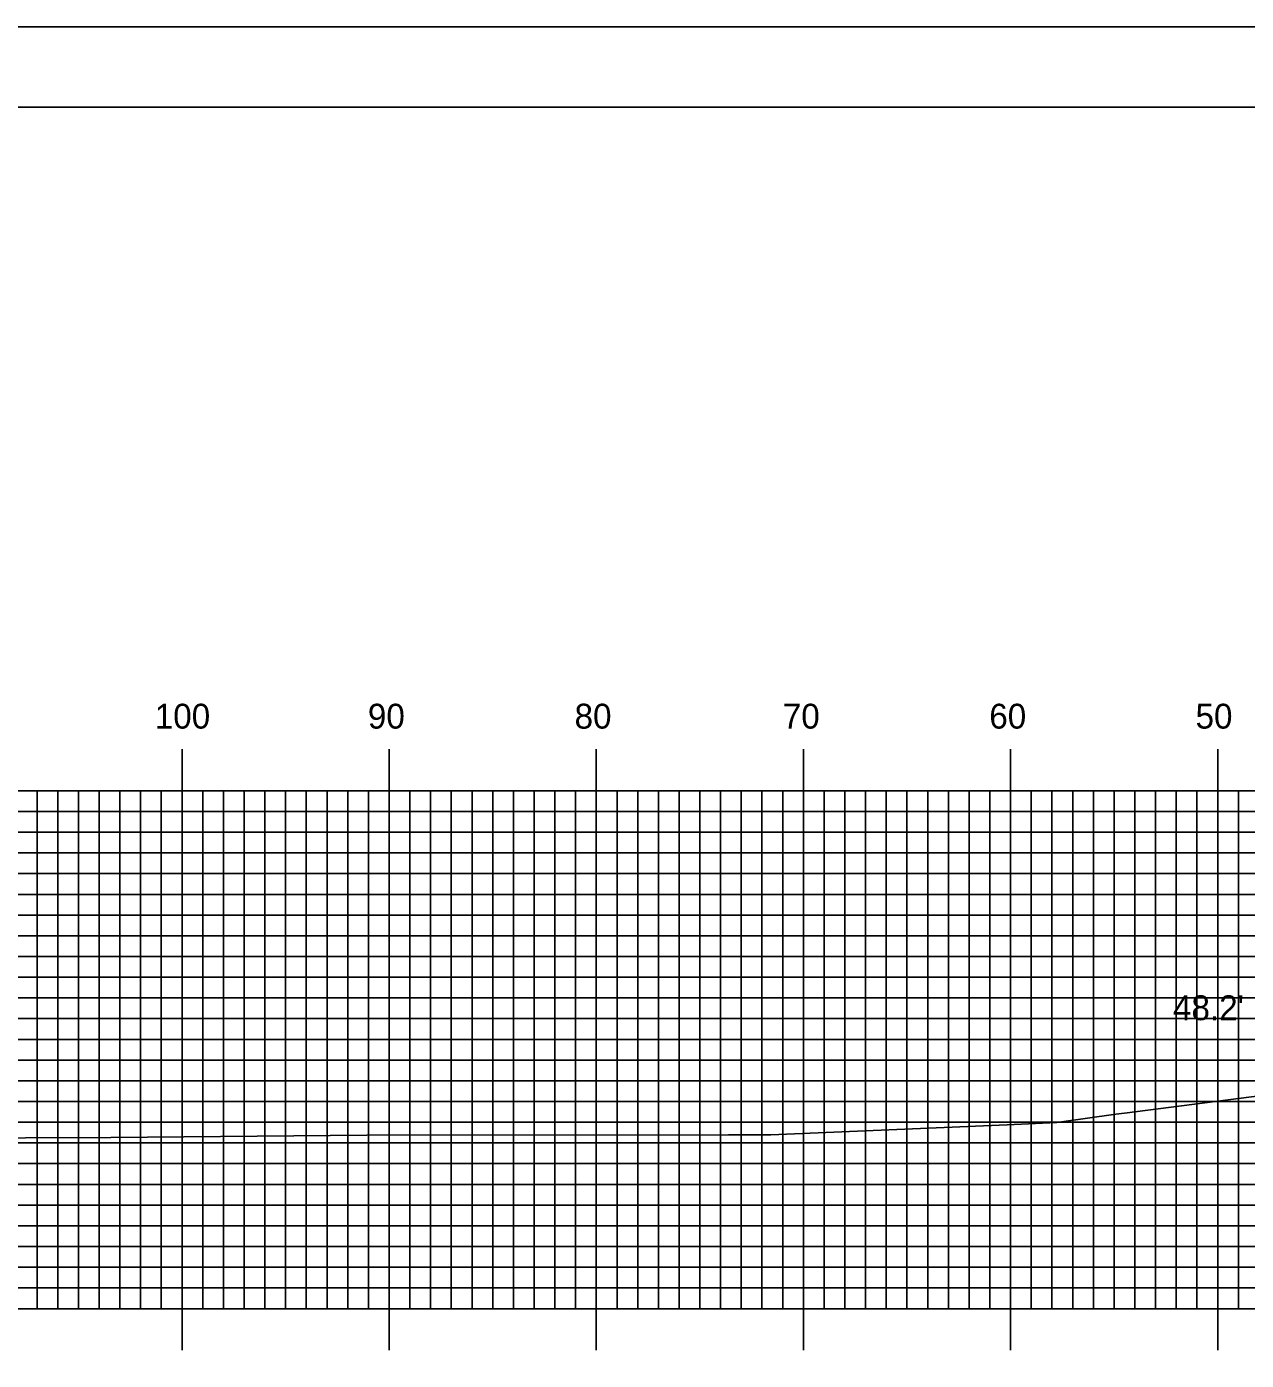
# Model space of a CAD drawing. Extents: x 1824360 to 1824703, y 442591 to 442811.
# Drawn here: x 1824417.8 to 1824476.7, y 442746.2 to 442810.5 of the extents above; entities that cross this region are included whole.
import ezdxf

# ---------------------------------------------------------------- set-up
doc = ezdxf.new("R2010")
doc.units = 0
for name, color, linetype in [('BORDER', 7, 'Continuous'), ('D_Text_Standard', 7, 'Continuous'), ('H_V ANNOTATION', 7, 'Continuous'), ('MAJOR', 7, 'Continuous'), ('MINOR', 7, 'Continuous'), ('PLOT BOUNDARY', 7, 'Continuous'), ('S_Roadway_Centerline', 7, 'Continuous')]:
    doc.layers.add(name, color=color, linetype=linetype)

msp = doc.modelspace()

# ---------------------------------------------------------------- linework, layer by layer
at = {"layer": 'BORDER'}
msp.add_lwpolyline([(1824375.735, 442596.665), (1824695.735, 442596.665), (1824695.735, 442806.665), (1824375.735, 442806.665)], close=True, dxfattribs=at)
at = {"layer": 'MAJOR'}
for p, q in [((1824425.335, 442775.669), (1824425.335, 442773.665)), ((1824435.335, 442775.669), (1824435.335, 442773.665)), ((1824445.335, 442775.669), (1824445.335, 442773.665)), ((1824455.335, 442775.669), (1824455.335, 442773.665)), ((1824465.335, 442775.669), (1824465.335, 442773.665)), ((1824475.335, 442775.669), (1824475.335, 442773.665)), ((1824385.335, 442773.665), (1824665.335, 442773.665)), ((1824385.335, 442773.665), (1824665.335, 442773.665)), ((1824425.335, 442748.665), (1824425.335, 442773.665)), ((1824435.335, 442748.665), (1824435.335, 442773.665)), ((1824445.335, 442748.665), (1824445.335, 442773.665)), ((1824455.335, 442748.665), (1824455.335, 442773.665)), ((1824465.335, 442748.665), (1824465.335, 442773.665)), ((1824475.335, 442748.665), (1824475.335, 442773.665)), ((1824385.335, 442768.665), (1824665.335, 442768.665)), ((1824385.335, 442763.665), (1824665.335, 442763.665)), ((1824385.335, 442758.665), (1824665.335, 442758.665)), ((1824385.335, 442753.665), (1824665.335, 442753.665)), ((1824385.335, 442748.665), (1824665.335, 442748.665)), ((1824385.335, 442748.665), (1824665.335, 442748.665)), ((1824425.335, 442746.661), (1824425.335, 442748.665)), ((1824435.335, 442746.661), (1824435.335, 442748.665)), ((1824445.335, 442746.661), (1824445.335, 442748.665)), ((1824455.335, 442746.661), (1824455.335, 442748.665)), ((1824465.335, 442746.661), (1824465.335, 442748.665)), ((1824475.335, 442746.661), (1824475.335, 442748.665))]:
    msp.add_line(p, q, dxfattribs=at)
at = {"layer": 'MINOR'}
for p, q in [((1824418.335, 442748.665), (1824418.335, 442773.665)), ((1824419.335, 442748.665), (1824419.335, 442773.665)), ((1824420.335, 442748.665), (1824420.335, 442773.665)), ((1824421.335, 442748.665), (1824421.335, 442773.665)), ((1824422.335, 442748.665), (1824422.335, 442773.665)), ((1824423.335, 442748.665), (1824423.335, 442773.665)), ((1824424.335, 442748.665), (1824424.335, 442773.665)), ((1824426.335, 442748.665), (1824426.335, 442773.665)), ((1824427.335, 442748.665), (1824427.335, 442773.665)), ((1824428.335, 442748.665), (1824428.335, 442773.665)), ((1824429.335, 442748.665), (1824429.335, 442773.665)), ((1824430.335, 442748.665), (1824430.335, 442773.665)), ((1824431.335, 442748.665), (1824431.335, 442773.665)), ((1824432.335, 442748.665), (1824432.335, 442773.665)), ((1824433.335, 442748.665), (1824433.335, 442773.665)), ((1824434.335, 442748.665), (1824434.335, 442773.665)), ((1824436.335, 442748.665), (1824436.335, 442773.665)), ((1824437.335, 442748.665), (1824437.335, 442773.665)), ((1824438.335, 442748.665), (1824438.335, 442773.665)), ((1824439.335, 442748.665), (1824439.335, 442773.665)), ((1824440.335, 442748.665), (1824440.335, 442773.665)), ((1824441.335, 442748.665), (1824441.335, 442773.665)), ((1824442.335, 442748.665), (1824442.335, 442773.665)), ((1824443.335, 442748.665), (1824443.335, 442773.665)), ((1824444.335, 442748.665), (1824444.335, 442773.665)), ((1824446.335, 442748.665), (1824446.335, 442773.665)), ((1824447.335, 442748.665), (1824447.335, 442773.665)), ((1824448.335, 442748.665), (1824448.335, 442773.665)), ((1824449.335, 442748.665), (1824449.335, 442773.665)), ((1824450.335, 442748.665), (1824450.335, 442773.665)), ((1824451.335, 442748.665), (1824451.335, 442773.665)), ((1824452.335, 442748.665), (1824452.335, 442773.665)), ((1824453.335, 442748.665), (1824453.335, 442773.665)), ((1824454.335, 442748.665), (1824454.335, 442773.665)), ((1824456.335, 442748.665), (1824456.335, 442773.665)), ((1824457.335, 442748.665), (1824457.335, 442773.665)), ((1824458.335, 442748.665), (1824458.335, 442773.665)), ((1824459.335, 442748.665), (1824459.335, 442773.665)), ((1824460.335, 442748.665), (1824460.335, 442773.665)), ((1824461.335, 442748.665), (1824461.335, 442773.665)), ((1824462.335, 442748.665), (1824462.335, 442773.665)), ((1824463.335, 442748.665), (1824463.335, 442773.665)), ((1824464.335, 442748.665), (1824464.335, 442773.665)), ((1824466.335, 442748.665), (1824466.335, 442773.665)), ((1824467.335, 442748.665), (1824467.335, 442773.665)), ((1824468.335, 442748.665), (1824468.335, 442773.665)), ((1824469.335, 442748.665), (1824469.335, 442773.665)), ((1824470.335, 442748.665), (1824470.335, 442773.665)), ((1824471.335, 442748.665), (1824471.335, 442773.665)), ((1824472.335, 442748.665), (1824472.335, 442773.665)), ((1824473.335, 442748.665), (1824473.335, 442773.665)), ((1824474.335, 442748.665), (1824474.335, 442773.665)), ((1824476.335, 442748.665), (1824476.335, 442773.665)), ((1824385.335, 442772.665), (1824665.335, 442772.665)), ((1824385.335, 442771.665), (1824665.335, 442771.665)), ((1824385.335, 442770.665), (1824665.335, 442770.665)), ((1824385.335, 442769.665), (1824665.335, 442769.665)), ((1824385.335, 442767.665), (1824665.335, 442767.665)), ((1824385.335, 442766.665), (1824665.335, 442766.665)), ((1824385.335, 442765.665), (1824665.335, 442765.665)), ((1824385.335, 442764.665), (1824665.335, 442764.665)), ((1824385.335, 442762.665), (1824665.335, 442762.665)), ((1824385.335, 442761.665), (1824665.335, 442761.665)), ((1824385.335, 442760.665), (1824665.335, 442760.665)), ((1824385.335, 442759.665), (1824665.335, 442759.665)), ((1824385.335, 442757.665), (1824665.335, 442757.665)), ((1824385.335, 442756.665), (1824665.335, 442756.665)), ((1824385.335, 442755.665), (1824665.335, 442755.665)), ((1824385.335, 442754.665), (1824665.335, 442754.665)), ((1824385.335, 442752.665), (1824665.335, 442752.665)), ((1824385.335, 442751.665), (1824665.335, 442751.665)), ((1824385.335, 442750.665), (1824665.335, 442750.665)), ((1824385.335, 442749.665), (1824665.335, 442749.665))]:
    msp.add_line(p, q, dxfattribs=at)
at = {"layer": 'PLOT BOUNDARY'}
msp.add_lwpolyline([(1824359.548, 442590.547), (1824699.548, 442590.547), (1824699.548, 442810.547), (1824359.548, 442810.547)], close=True, dxfattribs=at)
at = {"layer": 'S_Roadway_Centerline'}
msp.add_lwpolyline([(1824385.335, 442757.565), (1824409.533, 442756.886), (1824421.894, 442756.92), (1824434.264, 442757.04), (1824451.719, 442757.049), (1824453.755, 442757.049), (1824465.166, 442757.543), (1824467.571, 442757.657), (1824470.412, 442758.058), (1824470.828, 442758.095), (1824478.097, 442759.032)], dxfattribs=at)

# ---------------------------------------------------------------- texts
at = {"layer": 'D_Text_Standard'}
msp.add_text("48.2'", height=1.2, dxfattribs=at).set_placement((1824473.176, 442762.591))
at = {"layer": 'H_V ANNOTATION'}
for s, p in [('100', (1824424.018, 442776.665)), ('90', (1824434.307, 442776.665)), ('80', (1824444.286, 442776.665)), ('70', (1824454.339, 442776.665)), ('60', (1824464.307, 442776.665)), ('50', (1824474.264, 442776.665))]:
    msp.add_text(s, height=1.2, dxfattribs=at).set_placement(p)

doc.saveas('drawing.dxf')
